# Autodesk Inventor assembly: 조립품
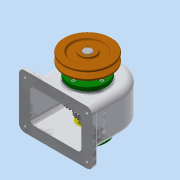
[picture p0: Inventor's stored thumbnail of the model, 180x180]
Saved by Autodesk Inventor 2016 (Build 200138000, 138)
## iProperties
Created: 2018-11
Part Number: 조립품
Material: 일반
Document SubType Name: Assembly
Designer: 공506_39
Author: 공506_39
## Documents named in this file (14)
- C:\Users\공506_39\Desktop\481111V1001\조립품.iam
- C:\Users\공506_39\Desktop\481111V1001\V-벨트풀리.ipt
- C:\Users\공506_39\Desktop\481111V1001\뒤커버.ipt
- C:\Users\공506_39\Desktop\481111V1001\멈춤나사 M4.ipt
- C:\Users\공506_39\Desktop\481111V1001\베어링 6203.ipt
- C:\Users\공506_39\Desktop\481111V1001\본체.ipt
- C:\Users\공506_39\Desktop\481111V1001\볼트 M4.ipt
- C:\Users\공506_39\Desktop\481111V1001\부시.ipt
- C:\Users\공506_39\Desktop\481111V1001\스퍼기어.ipt
- C:\Users\공506_39\Desktop\481111V1001\앞커버.ipt
- C:\Users\공506_39\Desktop\481111V1001\오일 실 28 40 8.ipt
- C:\Users\공506_39\Desktop\481111V1001\축.ipt
- C:\Users\공506_39\Desktop\481111V1001\키 5x5x18.ipt
- C:\Users\공506_39\Desktop\481111V1001\키 6x6x22.ipt
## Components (1 placed, 1 different names)
1. V-벨트풀리:1
